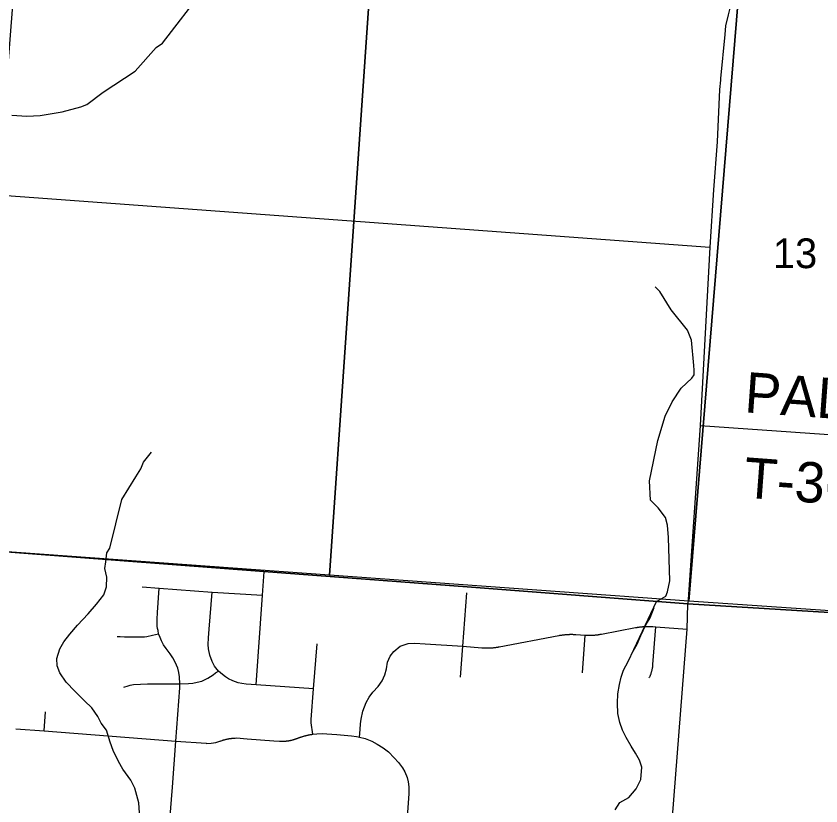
# Model space of a CAD drawing. Extents: x 0 to 34, y 0 to 22.
# Drawn here: x 3.646 to 4.778, y 15.479 to 16.59 of the extents above; entities that cross this region are included whole.
import ezdxf

# ---------------------------------------------------------------- set-up
doc = ezdxf.new("R2010")
doc.units = 0
for name, color, linetype in [('GM_X_Corporation', 7, 'Continuous'), ('GM_X_Minor_River', 7, 'Continuous'), ('GM_X_Section', 7, 'Continuous'), ('GM_X_Section_Text', 7, 'Continuous'), ('GM_X_Township_Road', 7, 'Continuous'), ('GM_X_Township_Road_Text', 7, 'Continuous'), ('SH_Cut_Line', 7, 'Continuous')]:
    doc.layers.add(name, color=color, linetype=linetype)

msp = doc.modelspace()

# ---------------------------------------------------------------- linework, layer by layer
at = {"layer": 'GM_X_Corporation'}
msp.add_lwpolyline([(2.1, 15.9442), (2.1, 14.1), (4.9875, 14.1), (5.0611, 15.2147), (5.0952, 15.7318), (4.92, 15.7429), (4.5905, 15.7634), (4.2803, 15.787), (3.9945, 15.8088), (3.3132, 15.8609), (2.8362, 15.8952), (2.7799, 15.8989), (2.6921, 15.9056), (2.5827, 15.9132), (2.2903, 15.9292)], close=True, dxfattribs=at)
msp.add_lwpolyline([(3.3132, 15.8609), (3.9945, 15.8088), (4.2803, 15.787), (4.5905, 15.7634), (4.92, 15.7429), (5.0952, 15.7318), (5.9419, 15.6782), (6.1109, 15.6683), (6.4, 15.6498), (6.624, 15.6351), (6.838, 15.6206)], dxfattribs=at)
at = {"layer": 'GM_X_Minor_River'}
for points in [[(3.6401, 16.4503), (3.6613, 16.4491), (3.6799, 16.4502), (3.7109, 16.4551), (3.7374, 16.4622), (3.7458, 16.4656), (3.7689, 16.483), (3.8137, 16.5122), (3.8433, 16.5455), (3.852, 16.5519), (3.9105, 16.6281)], [(4.5468, 15.7663), (4.5596, 15.7739), (4.5623, 15.78), (4.5654, 15.7955), (4.5636, 15.8566), (4.5621, 15.8737), (4.5591, 15.8844), (4.5489, 15.8981), (4.538, 15.9091), (4.5369, 15.9361), (4.5487, 15.993), (4.559, 16.0271), (4.5685, 16.0472), (4.5815, 16.0666), (4.5963, 16.0806), (4.5997, 16.0855), (4.5997, 16.092), (4.5993, 16.0984), (4.596, 16.1341), (4.5903, 16.1482), (4.5673, 16.1767), (4.5511, 16.2026), (4.5446, 16.209)], [(3.7725, 15.8221), (3.7736, 15.8349), (3.7782, 15.8413), (3.795, 15.91), (3.8144, 15.9419), (3.8216, 15.9532), (3.8254, 15.9623), (3.8364, 15.9764)], [(3.8197, 15.4694), (3.8187, 15.4834), (3.8162, 15.4937), (3.8133, 15.504), (3.8077, 15.5151), (3.7965, 15.5304), (3.7902, 15.5414), (3.7828, 15.5571), (3.7787, 15.5685), (3.7732, 15.5857), (3.7661, 15.5952), (3.7613, 15.6048), (3.7527, 15.617), (3.7426, 15.6266), (3.7288, 15.6404), (3.7168, 15.6531), (3.7078, 15.6661), (3.7041, 15.676), (3.7035, 15.6862), (3.7078, 15.6999), (3.7136, 15.7097), (3.7217, 15.7206), (3.7328, 15.733), (3.7474, 15.7492), (3.7592, 15.7627), (3.7696, 15.7759), (3.7735, 15.7869), (3.7737, 15.8005), (3.7708, 15.8131), (3.7725, 15.8221)], [(4.4884, 15.4734), (4.4949, 15.4836), (4.5075, 15.4907), (4.5182, 15.5031), (4.5248, 15.5163), (4.5258, 15.5334), (4.5225, 15.5433), (4.5173, 15.5529), (4.5109, 15.5632), (4.5042, 15.5754), (4.4987, 15.5853), (4.495, 15.5964), (4.4921, 15.6089), (4.4919, 15.6234), (4.4924, 15.6366), (4.4944, 15.6495), (4.4968, 15.6601), (4.5003, 15.67), (4.5069, 15.682), (4.5468, 15.7663)], [(4.5139, 15.6968), (4.5193, 15.7066), (4.5247, 15.7187), (4.5317, 15.7338), (4.5375, 15.7436), (4.5433, 15.758)]]:
    msp.add_lwpolyline(points, dxfattribs=at)
at = {"layer": 'GM_X_Section'}
for points in [[(3.6598, 16.8406), (4.1558, 16.8052), (4.0871, 15.8035), (3.5815, 15.8402)], [(4.1558, 16.8052), (4.6741, 16.7675), (4.5921, 15.7668), (4.0871, 15.8035)], [(4.6741, 16.7675), (5.1577, 16.7346), (5.0919, 15.7328), (4.5921, 15.7668)]]:
    msp.add_lwpolyline(points, close=True, dxfattribs=at)
at = {"layer": 'GM_X_Township_Road'}
for p, q in [((3.3231, 16.3603), (4.6218, 16.2647)), ((4.6218, 16.2647), (4.6081, 16.0142)), ((4.6081, 16.0142), (4.5907, 15.7628)), ((4.5455, 15.7308), (4.5897, 15.7276)), ((4.4424, 15.6662), (4.4463, 15.7191)), ((3.6859, 15.5845), (3.6874, 15.6111))]:
    msp.add_line(p, q, dxfattribs=at)
for points in [[(4.7365, 16.9075), (4.7349, 16.8816), (4.7327, 16.8601), (4.7287, 16.8354), (4.7226, 16.8114), (4.7174, 16.7948), (4.7099, 16.7734), (4.6996, 16.7473), (4.693, 16.7276), (4.6809, 16.6925), (4.666, 16.6508), (4.6578, 16.63), (4.6511, 16.6064), (4.6473, 16.5916), (4.6436, 16.576), (4.6429, 16.5638), (4.6368, 16.5019), (4.6366, 16.4999)], [(4.6366, 16.4999), (4.6353, 16.4867), (4.6318, 16.4129), (4.6268, 16.3453), (4.6218, 16.2647)], [(4.6081, 16.0142), (5.1107, 15.9789)], [(3.9838, 15.6492), (3.9925, 15.7752), (3.9948, 15.8083)], [(3.8237, 15.7872), (3.8473, 15.7854), (3.9217, 15.7796), (3.9925, 15.7752)], [(3.871, 15.57), (3.8767, 15.6452), (3.8766, 15.6508), (3.8761, 15.6607), (3.8751, 15.6667), (3.8735, 15.6726), (3.87, 15.6812), (3.8668, 15.6872), (3.8628, 15.6929), (3.8573, 15.7002), (3.8537, 15.7056), (3.8505, 15.7113), (3.8486, 15.7158), (3.8466, 15.721), (3.8459, 15.7258), (3.8453, 15.7285), (3.8448, 15.7319), (3.8447, 15.7361), (3.8448, 15.7418), (3.8453, 15.7508), (3.8473, 15.7854)], [(4.0646, 15.6437), (3.9838, 15.6492), (3.9696, 15.6502), (3.9638, 15.6509), (3.9584, 15.6521), (3.9509, 15.6548), (3.9448, 15.6577), (3.9407, 15.6605), (3.9364, 15.6639), (3.9306, 15.6687), (3.9254, 15.6753), (3.9217, 15.6822), (3.9187, 15.6909), (3.9169, 15.6999), (3.9165, 15.7061), (3.9169, 15.7153), (3.9178, 15.7276), (3.9217, 15.7796)], [(4.2711, 15.6599), (4.2743, 15.7034), (4.2799, 15.7785)], [(4.5525, 15.2537), (4.5897, 15.7276), (4.5907, 15.7628)], [(4.4463, 15.7191), (4.4471, 15.7191), (4.4478, 15.719), (4.4486, 15.719), (4.4493, 15.719), (4.4501, 15.719), (4.4508, 15.719), (4.4516, 15.719), (4.4524, 15.719), (4.4531, 15.719), (4.4539, 15.719), (4.4546, 15.719), (4.4554, 15.719), (4.4561, 15.7191), (4.4569, 15.7191), (4.4577, 15.7191), (4.4584, 15.7192), (4.4592, 15.7193), (4.4599, 15.7193), (4.4607, 15.7194), (4.4614, 15.7195), (4.4622, 15.7195), (4.4629, 15.7196), (4.4637, 15.7197), (4.4644, 15.7198), (4.4652, 15.7199), (4.4659, 15.72), (4.4667, 15.7202), (4.4674, 15.7203), (4.4682, 15.7204), (4.4693, 15.7206), (4.5171, 15.7297), (4.5178, 15.7298), (4.5186, 15.73), (4.5193, 15.7301), (4.5201, 15.7302), (4.5208, 15.7303), (4.5215, 15.7304), (4.5223, 15.7305), (4.523, 15.7306), (4.5238, 15.7307), (4.5246, 15.7308), (4.5253, 15.7309), (4.5261, 15.731), (4.5268, 15.731), (4.5276, 15.7311), (4.5283, 15.7311), (4.5291, 15.7312), (4.5298, 15.7312), (4.5306, 15.7313), (4.5314, 15.7313), (4.5321, 15.7313), (4.5329, 15.7313), (4.5336, 15.7313), (4.5344, 15.7314), (4.5351, 15.7314), (4.5359, 15.7313), (4.5367, 15.7313), (4.5374, 15.7313), (4.5382, 15.7313), (4.5389, 15.7313), (4.5397, 15.7312), (4.5404, 15.7312), (4.5415, 15.7311), (4.5455, 15.7308)], [(4.5365, 15.6592), (4.5368, 15.6598), (4.5371, 15.6605), (4.5375, 15.6612), (4.5378, 15.6619), (4.538, 15.6626), (4.5383, 15.6633), (4.5386, 15.664), (4.5389, 15.6647), (4.5391, 15.6654), (4.5393, 15.6661), (4.5396, 15.6669), (4.5398, 15.6676), (4.54, 15.6683), (4.5402, 15.669), (4.5404, 15.6698), (4.5405, 15.6705), (4.5407, 15.6713), (4.5409, 15.672), (4.541, 15.6727), (4.5411, 15.6735), (4.5413, 15.6742), (4.5414, 15.675), (4.5415, 15.6757), (4.5415, 15.6765), (4.5416, 15.6772), (4.5417, 15.678), (4.5455, 15.7308)], [(3.7882, 15.7173), (3.7928, 15.7171), (3.7987, 15.7168), (3.8066, 15.7168), (3.8153, 15.7166), (3.8223, 15.7167), (3.8268, 15.7169), (3.83, 15.7174), (3.838, 15.7189), (3.8466, 15.721)], [(4.2743, 15.7034), (4.3012, 15.7014), (4.302, 15.7013), (4.3027, 15.7013), (4.3035, 15.7012), (4.3042, 15.7012), (4.305, 15.7012), (4.3057, 15.7011), (4.3065, 15.7011), (4.3073, 15.7011), (4.308, 15.7011), (4.3088, 15.7011), (4.3095, 15.7011), (4.3103, 15.7011), (4.311, 15.7011), (4.3118, 15.7012), (4.3126, 15.7012), (4.3133, 15.7012), (4.3141, 15.7013), (4.3148, 15.7013), (4.3156, 15.7014), (4.3163, 15.7015), (4.3171, 15.7015), (4.3178, 15.7016), (4.3186, 15.7017), (4.3193, 15.7018), (4.3201, 15.7018), (4.3209, 15.7019), (4.3216, 15.7021), (4.3224, 15.7022), (4.3231, 15.7023), (4.3238, 15.7024), (4.3246, 15.7025), (4.3253, 15.7027), (4.4091, 15.7186), (4.4099, 15.7187), (4.4106, 15.7189), (4.4113, 15.719), (4.4121, 15.7191), (4.4128, 15.7192), (4.4136, 15.7193), (4.4143, 15.7195), (4.4151, 15.7195), (4.4158, 15.7196), (4.4166, 15.7197), (4.4174, 15.7198), (4.4181, 15.7199), (4.4189, 15.7199), (4.4196, 15.72), (4.4204, 15.7201), (4.4211, 15.7201), (4.4219, 15.7201), (4.4226, 15.7202), (4.4234, 15.7202), (4.4242, 15.7202), (4.4249, 15.7203), (4.4257, 15.7203), (4.4264, 15.7203), (4.4272, 15.7203), (4.4279, 15.7203), (4.4287, 15.7203), (4.4295, 15.7202), (4.4302, 15.7202), (4.431, 15.7202), (4.4317, 15.7201), (4.4325, 15.7201), (4.4332, 15.7201), (4.4463, 15.7191)], [(4.0634, 15.5798), (4.0613, 15.5957), (4.0612, 15.6003), (4.0646, 15.6437), (4.0697, 15.7069)], [(4.1292, 15.5757), (4.13, 15.5863), (4.1307, 15.5943), (4.1313, 15.6008), (4.1338, 15.6122), (4.1385, 15.6244), (4.1427, 15.6317), (4.1478, 15.6387), (4.1554, 15.647), (4.1611, 15.655), (4.1647, 15.6631), (4.1668, 15.6719), (4.1684, 15.6811), (4.1722, 15.6897), (4.1772, 15.6963), (4.1864, 15.7034), (4.1974, 15.7074), (4.207, 15.708), (4.2216, 15.707), (4.2743, 15.7034)], [(3.8766, 15.6508), (3.8886, 15.6512), (3.8948, 15.6517), (3.901, 15.6528), (3.9072, 15.6546), (3.9113, 15.6562), (3.9156, 15.6586), (3.9197, 15.6611), (3.9232, 15.6634), (3.9266, 15.6659), (3.9306, 15.6687)], [(3.7977, 15.646), (3.8036, 15.6479), (3.8066, 15.6488), (3.8111, 15.6496), (3.8311, 15.6508), (3.8766, 15.6508)], [(3.6457, 15.5875), (3.6859, 15.5845), (3.871, 15.57), (3.9136, 15.567), (3.9145, 15.5669), (3.9207, 15.5671), (3.9269, 15.568), (3.9327, 15.57), (3.9333, 15.5702), (3.934, 15.5704), (3.9348, 15.5707), (3.9358, 15.571), (3.9365, 15.5713), (3.9372, 15.5715), (3.9379, 15.5717), (3.9387, 15.5719), (3.9394, 15.5721), (3.9401, 15.5723), (3.9409, 15.5725), (3.9416, 15.5727), (3.9423, 15.5729), (3.9431, 15.573), (3.9438, 15.5732), (3.9446, 15.5733), (3.9453, 15.5734), (3.946, 15.5736), (3.9468, 15.5737), (3.9476, 15.5738), (3.9483, 15.5739), (3.9491, 15.5739), (3.9498, 15.574), (3.9506, 15.5741), (3.9513, 15.5741), (3.9521, 15.5742), (3.9528, 15.5742), (3.9536, 15.5742), (3.9543, 15.5742), (3.9562, 15.5746), (3.9713, 15.5732), (4.0088, 15.5706), (4.0167, 15.5701), (4.0175, 15.57), (4.0183, 15.57), (4.0191, 15.57), (4.0198, 15.57), (4.0206, 15.57), (4.0213, 15.57), (4.0221, 15.57), (4.0228, 15.57), (4.0236, 15.57), (4.0244, 15.5701), (4.0251, 15.5701), (4.0259, 15.5702), (4.0266, 15.5703), (4.0274, 15.5704), (4.0281, 15.5705), (4.0289, 15.5706), (4.0296, 15.5707), (4.0304, 15.5708), (4.0311, 15.5709), (4.0319, 15.5711), (4.0326, 15.5712), (4.0333, 15.5714), (4.0341, 15.5716), (4.0348, 15.5718), (4.0356, 15.572), (4.0363, 15.5722), (4.037, 15.5724), (4.0377, 15.5726), (4.0385, 15.5728), (4.0392, 15.5731), (4.0399, 15.5733), (4.0406, 15.5736), (4.0413, 15.5739), (4.0422, 15.5742), (4.043, 15.5745), (4.0437, 15.5748), (4.0444, 15.575), (4.0451, 15.5753), (4.0458, 15.5756), (4.0465, 15.5758), (4.0472, 15.576), (4.048, 15.5763), (4.0487, 15.5765), (4.0494, 15.5767), (4.0501, 15.5769), (4.0509, 15.5771), (4.0516, 15.5774), (4.0523, 15.5776), (4.053, 15.5777), (4.0538, 15.5779), (4.0545, 15.5781), (4.0553, 15.5783), (4.056, 15.5785), (4.0567, 15.5786), (4.0575, 15.5788), (4.0582, 15.5789), (4.059, 15.5791), (4.0597, 15.5792), (4.0605, 15.5793), (4.0612, 15.5795), (4.0619, 15.5796), (4.0627, 15.5797), (4.0634, 15.5798), (4.0693, 15.5805), (4.0767, 15.5808), (4.0833, 15.5805), (4.0973, 15.5794), (4.118, 15.5777), (4.1249, 15.5766), (4.1292, 15.5757), (4.1369, 15.5736), (4.1462, 15.5699), (4.154, 15.566), (4.1623, 15.5607), (4.1697, 15.5548), (4.1779, 15.5467), (4.1838, 15.5398), (4.1894, 15.5325), (4.1927, 15.5268), (4.1959, 15.5191), (4.1975, 15.5128), (4.1985, 15.5059), (4.1985, 15.4966), (4.1835, 15.2821)], [(3.8845, 15.3609), (3.8794, 15.3667), (3.8747, 15.372), (3.8707, 15.3768), (3.8672, 15.3821), (3.8642, 15.3877), (3.8618, 15.3936), (3.86, 15.3996), (3.8591, 15.4052), (3.859, 15.4105), (3.8593, 15.4186), (3.86, 15.4291), (3.8622, 15.4589), (3.866, 15.5055), (3.871, 15.57)]]:
    msp.add_lwpolyline(points, dxfattribs=at)
at = {"layer": 'SH_Cut_Line'}
for points in [[(8.9, 15.4827), (8.9, 20.9), (2.1, 20.9), (2.1, 15.9442), (2.2903, 15.9292), (2.5827, 15.9132), (2.6921, 15.9056), (2.7799, 15.8989), (2.8362, 15.8952), (3.3132, 15.8609), (3.9945, 15.8088), (4.2803, 15.787), (4.5905, 15.7634), (4.92, 15.7429), (5.0952, 15.7318), (5.9419, 15.6782), (6.1109, 15.6683), (6.4, 15.6498), (6.624, 15.6351), (6.838, 15.6206), (7.6503, 15.5653), (8.6741, 15.4976)], [(2.1, 15.9442), (2.1, 14.1), (8.9, 14.1), (8.9, 15.4827), (8.6741, 15.4976), (7.6503, 15.5653), (6.838, 15.6206), (6.624, 15.6351), (6.4, 15.6498), (6.1109, 15.6683), (5.9419, 15.6782), (5.0952, 15.7318), (4.92, 15.7429), (4.5905, 15.7634), (4.2803, 15.787), (3.9945, 15.8088), (3.3132, 15.8609), (2.8362, 15.8952), (2.7799, 15.8989), (2.6921, 15.9056), (2.5827, 15.9132), (2.2903, 15.9292)]]:
    msp.add_lwpolyline(points, close=True, dxfattribs=at)

# ---------------------------------------------------------------- texts
at = {"layer": 'GM_X_Section_Text'}
msp.add_text('13', height=0.04186, rotation=0, dxfattribs=at).set_placement((4.7103, 16.2353))
at = {"layer": 'GM_X_Township_Road_Text'}
for s, rotation, p in [('PALMER', 355.9261, (4.6693, 16.0326)), ('T-36', 355.737, (4.6679, 15.9127))]:
    msp.add_text(s, height=0.05682, rotation=rotation, dxfattribs=at).set_placement(p)

doc.saveas('drawing.dxf')
